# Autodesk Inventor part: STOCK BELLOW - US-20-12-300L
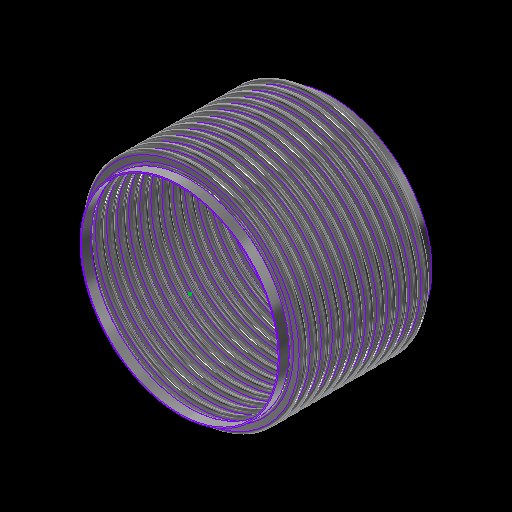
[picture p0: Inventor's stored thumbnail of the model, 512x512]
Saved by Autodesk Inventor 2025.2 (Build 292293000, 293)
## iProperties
Category: 16 GA (0.060 THICK)
RuleStatus: InUse
Created: 2024-01
Part Number: STOCK BELLOW - US-20-12-300L
Project: =STOCK BELLOWS: <Stock Number><SFILL>
Material: ASTM A240-304
Description: =STOCK BELLOWS: <Stock Number>, <SID_> I.D., <SOD_> O.D., <SPLY_> PLY, <Category>, <SNET_CONS> CONS.<PITCH_><STANGENT_> TANGENT<SFILL>
Document SubType Name: Sheet Metal
Designer: GS
Stock Number: U.S-20-12-300L
Surface Area: 31923.8 cm^2
Volume: 4820.44 cm^3
Sheet Metal Rule: Default
Appearance: STAINLESS STEEL
Mass: 38839.7 g
Density: 8.05729 g/cm^3
THK: 0.036
ID: 3.500
OD: 4.250
CONS_: 2
PITCH: 0.500
TANGENT: 0.500
BELLOWS_UPSET: 0.000
d79: 1.000
d82: 1.000
d83: 26.000
d84: 24.000
d174: 8
d214: 8
STHK_: 0.060
SID_: 20.000
SOD_: 22.500
SPITCH_: 1.125
STANGENT__: 1.000
SBELLOWS_UPSET_: 0.000
SDIFF_TAN: 1.000
d252: 2
d275: 2
d287: 0.050
d289: 0.500
d290: 0.000
SOD_NECK: 20 1/4
PLY: 1
PSET: 4.178
PBAR: 1.035
COUNTER: 1.500
NET_TUBE: 3.071
CONS: 2
S_CONS: 0
NET_CONS: 2
ID_M: 88.90 mm
OD_M: 107.95 mm
THK_M: 0.91 mm
ID_U: 3.500 in
OD_U: 4.250 in
THK_U: 0.036 in
TANGENT2: 0.500
TAN_TO_TAN: 1.000 in
d80: 2.571
d81: 10
SID: 2.375
SCONS_: 12
SPITCH: 0.250
STANGENT_: 1.000
SBELLOWS_UPSET: 0.000
SNET_CONS: 12
SS_CONS: 0
SCONS: 8
d190: 8
d191: 1
d192: 1
d193: 8
d194: 0
SIZE: 20.00
PRESSURE: 300
d230: 8
STANGENT: 4.000
SPLY_: 2
d233: 8
d234: 0
d263: 2
d265: 1
d268: 2
d269: 0
d286: 2
d288: 1
d291: 2
d292: 0
SREROLL: 0.750
BLETP: 1.000 ul
PRES_Copy: 85
MATTABLE: 20 GA (0.036 THICK)
PART_NUMBER: U.S-20-12-300L
PITCH_: =, <SPITCH_> PITCH,
CFILL: .
SFILL: .
MESH: ,
COMP: 2.27
EXT: 1.14
LAT: 0.48
ANG: 573
ASR: 7893
LSR: 29335
ANSR: 7776
PRES: 300
COMPM: 22.7
EXTM: 11.35
LATM: 4.80
ASRM: 1382.301
PRESM: 20.684
LSRM: 5137.439
ANSRM: 1361.811
TEMPMIN: 20
TEMPMAX: 800
TEMPMINM: -7
TEMPMAXM: 427
WEIGHTM: 38.840
WEIGHT: 85.627
Author: GS
Keywords: 20 GA (0.036 THICK)
Comments: =STOCK BELLOW - <STOCK NUMBER>
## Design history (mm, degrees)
sketch "Sketch2"
  geometry: L1 (0, -177.245)-(0, 562.856) reference; L2 (45.364, 0)-(44.45, 0); L3 (48.082, -2.718)-(50.343, -2.718); L4 (48.082, -3.632)-(50.343, -3.632); L5 (50.343, -9.982)-(48.082, -9.982); L6 (50.343, -9.068)-(48.082, -9.068); L7 (45.364, -12.7)-(44.45, -12.7); L8 (48.082, 0)-(48.082, -12.7); L9 (50.343, -6.35)-(53.975, -6.35); L10 (44.45, 0)-(44.45, -12.7); L11 (20.376, 102.841)-(20.376, 101.926); L12 (58.262, 457.127)-(58.262, 349.177); L13 (58.262, 444.427)-(58.262, 336.477); L14 (93.133, -58.817)-(93.133, -71.517); L15 (118.746, -66.401)-(118.746, -66.401); L16 (50.343, -9.068)-(50.343, -9.982); L17 (48.082, -9.068)-(48.082, -9.982); L18 (48.082, -9.525)-(50.343, -9.525); L19 (53.975, 0)-(53.975, -12.7); L20 (-50.343, -9.068)-(-50.343, -9.982); L21 (-50.343, -2.718)-(-48.082, -2.718); L22 (-50.343, -3.632)-(-48.082, -3.632); L23 (-48.082, -9.068)-(-50.343, -9.068); L24 (-50.343, -9.525)-(-48.082, -9.525); L25 (-48.082, -9.982)-(-50.343, -9.982); L26 (-48.082, -9.068)-(-48.082, -9.982); L27 (-44.45, 0.653)-(-44.45, -12.047); L28 (-48.082, -6.35)-(-44.45, -6.35); L29 (-50.343, 0.653)-(-50.343, -12.7); L30 (-53.061, 0)-(-53.975, 0); L31 (-53.975, 0)-(-53.975, -12.7); L32 (-53.061, -12.7)-(-53.975, -12.7); A1 r 2.718 centre (48.082, 0) between (45.364, 0) and (48.082, -2.718); A2 r 3.632 centre (48.082, 0) between (44.45, 0) and (48.082, -3.632); A3 r 3.632 centre (50.343, -6.35) between (50.343, -9.982) and (50.343, -2.718); A4 r 2.718 centre (50.343, -6.35) between (50.343, -9.068) and (50.343, -3.632); A5 r 2.718 centre (48.082, -12.7) between (48.082, -9.982) and (45.364, -12.7); A6 r 3.632 centre (48.082, -12.7) between (48.082, -9.068) and (44.45, -12.7); A7 r 3.175 centre (50.343, -6.35) between (50.343, -9.525) and (53.518, -6.35); A8 r 3.175 centre (48.082, -12.7) between (48.082, -9.525) and (44.907, -12.7); A9 r 2.718 centre (-50.343, -12.7) between (-50.343, -9.982) and (-53.061, -12.7); A10 r 2.718 centre (-48.082, -6.35) between (-48.082, -9.068) and (-48.082, -3.632); A11 r 3.175 centre (-48.082, -6.35) between (-48.082, -9.525) and (-44.907, -6.35); A12 r 3.632 centre (-48.082, -6.35) between (-48.082, -9.982) and (-48.082, -2.718); A13 r 3.175 centre (-50.343, -12.7) between (-50.343, -9.525) and (-53.518, -12.7); A14 r 3.632 centre (-50.343, -12.7) between (-50.343, -9.068) and (-53.975, -12.7); A15 r 2.718 centre (-50.343, 0) between (-53.061, 0) and (-50.343, -2.718); A16 r 3.632 centre (-50.343, 0) between (-53.975, 0) and (-50.343, -3.632); 10 further points
  constraints: 62 end point, 38 point on circle, 20 tangent, 16 centre point, 12 parallel, 9 midpoint, 7 vertical, 6 coincident, 6 concentric, 6 point on line, 4 equal radius, 4 perpendicular, 3 horizontal, 1 collinear, 1 horizontal alignment, 10 other
  dimensions: "THK" = 0.9144 distance of L11.start L11.end; "ID" = 88.9 distance of L11.end point (20.376, 13.026); "OD" = 107.95 distance of L12.start L12.end; "PITCH" = 12.7 distance of L12.start L13.start; "TANGENT" = 12.7 distance of L14.start L14.end; "BELLOWS_UPSET" = 0 distance of L15.start L15.end; "d43" = 88.9 diameter of L10 L1 (= ID); "d44" = 107.95 diameter of L9.end L1 (= OD); "d45" = 0.9144 distance between parallel lines of L5 L6 (computed from THK, PLY); "d46" = 3.6322 radius of A3 (computed from PITCH, THK, PLY); "UPSET_PITCH" = 12.7 distance of L2.end L7.end (derived); "SIDEWALL_ANGLE" = 360 deg dimension on L3 L9 (derived); "CON_GAP" = 5.4356 distance of point (48.082, -9.068) point (48.082, -3.632) (derived); "TAN1" = 4.98728 dimension on A8 (derived); "TAN2" = 4.98728 dimension on A7 (derived); "LEG1" = 2.2606 distance of L18.start L18.end (derived); "d278" = 0.9144 distance between parallel lines of L25 L23 (derived); "d279" = 3.6322 radius of A12 (derived); "d280" = 12.7 distance of L30.end L31.end (derived); "d281" = 360 deg dimension on L21 L28 (derived); "d282" = 5.4356 distance of point (-50.343, -9.068) point (-50.343, -3.632) (derived); "d283" = 4.98728 dimension on A13 (derived); "d284" = 4.98728 dimension on A11 (derived); "d285" = 2.2606 distance of L24.start L24.end (derived); "d293" = 88.9 diameter of L27 L1 (derived); "d294" = 107.95 diameter of L31 L1 (derived)
  node "Sketch Rectangular Pattern1" dims "d31" = 25.4, "ID" = 88.9
  node "Sketch Rectangular Pattern2" dims "d39" = 25.4, "PITCH" = 12.7
revolve "CONS" stored, may be unused: angle "d48" = 90 deg
node "BELLOW MIDPLANE"
pattern_linear "Rectangular Pattern2" dims "d52" = 12.7 (= UPSET_PITCH)
sketch "Sketch5"
  geometry: C1 r 45.364 at (0, 0) reference; C2 r 44.45 at (0, 0) reference
extrude "TANGENT" new body sketch "Sketch5" distance "d53" = 12.7 (= TANGENT); taper "d54" = 0 deg
revolve "SAMETAN" stored, may be unused: angle "d65" = 90 deg
revolve "DIFFTAN" stored, may be unused: angle "d70" = 90 deg
sketch "Sketch9"
  geometry: L1 (53.319, 0)-(-53.319, 0) reference; L2 (0, -17.78)-(0, 17.78) reference; L3 (38.085, 0)-(-38.085, 0); L4 (38.085, -11.906)-(38.085, 11.906); L5 (25.385, -11.906)-(25.385, 11.906); L6 (13.15, 11.906)-(13.15, -11.906); L7 (-25.385, -11.906)-(-25.385, 11.906); L8 (-38.085, -11.906)-(-38.085, 11.906); L9 (37.291, -11.906)-(37.291, 11.906); L10 (38.085, -11.906)-(37.291, -11.906); L11 (38.085, 11.906)-(37.291, 11.906); L12 (13.546, 11.906)-(12.753, 11.906); L13 (12.753, 11.906)-(12.753, -11.906); L14 (12.753, -11.906)-(13.546, -11.906); L15 (13.546, -11.906)-(13.546, 11.906); L16 (-13.546, 11.906)-(-13.546, -11.906); L17 (-13.15, 11.906)-(-13.15, -11.906); L18 (-13.546, -11.906)-(-12.753, -11.906); L19 (-12.753, -11.906)-(-12.753, 11.906); L20 (-12.753, 11.906)-(-13.546, 11.906); L21 (-38.085, -11.906)-(-37.291, -11.906); L22 (-37.291, -11.906)-(-37.291, 11.906); L23 (-37.291, 11.906)-(-38.085, 11.906); L24 (-38.085, 11.906)-(-38.085, -11.906); L25 (38.085, -0.397)-(-38.085, -0.397); L26 (-38.085, -0.397)-(-38.085, 0.397); L27 (-38.085, 0.397)-(38.085, 0.397); L28 (38.085, 0.397)-(38.085, -0.397); L29 (-38.085, 11.906)-(38.085, 11.906); L30 (38.085, 11.906)-(38.085, 12.7); L31 (38.085, 12.7)-(-38.085, 12.7); L32 (-38.085, 12.7)-(-38.085, 11.906); L33 (38.085, -11.906)-(-38.085, -11.906); L34 (-38.085, -11.906)-(-38.085, -12.7); L35 (-38.085, -12.7)-(38.085, -12.7); L36 (38.085, -12.7)-(38.085, -11.906); 30 further points
  constraints: 68 end point, 13 midpoint, 13 parallel, 8 horizontal, 7 perpendicular, 6 equal length, 3 point on line, 2 vertical, 14 other
  dimensions: "d115" = 23.8125 distance of L4.start L4.end (derived); "d116" = 12.7 distance between parallel lines of L4 L5 (derived); "d117" = 12.23516 distance between parallel lines of L5 L6 (derived); "d125" = 38.53427 distance between parallel lines of L7 L6 (derived); "d127" = 12.7 distance between parallel lines of L8 L7 (derived); "d128" = 24.93516 distance between parallel lines of L6 L4 (derived); "d130" = 76.16943 distance between parallel lines of L8 L4 (derived); "RULER_THK" = 0.79375 distance between parallel lines of L4 L9; "d135" = 0.79375 distance of L13.end L14.end (derived); "d138" = 26.29911 distance of L13.end L16.end (derived); "d143" = 0.79375 distance of L22.end L8.end (derived); "d144" = 0.79375 distance between parallel lines of L27 L25 (derived)
extrude "RULER" join sketch "Sketch9" distance "d149" = 0.79375 (derived); taper "d150" = 0 deg
extrude "BARS" join sketch "Sketch9" distance "d151" = 0.79375 (derived); taper "d152" = 0 deg
pattern_linear "Rectangular Pattern4" dims "d155" = 26.29911 (derived)
sketch "Sketch13"
  geometry: L1 (93.149, -52.467)-(93.149, -77.867); L2 (257.048, 0)-(254, 0); L3 (257.048, -28.575)-(254, -28.575); L4 (277.082, -22.955)-(262.668, -22.955); L5 (277.082, -19.907)-(262.668, -19.907); L6 (277.082, -14.287)-(285.75, -14.287); L7 (262.668, -5.62)-(277.082, -5.62); L8 (262.668, 0)-(262.668, -28.575); L9 (254, 0)-(254, -28.575); L10 (58.254, 75.069)-(58.254, -496.431); L11 (58.254, 46.494)-(58.254, -525.006); L12 (58.254, -10.656)-(58.254, -582.156); L13 (58.254, -39.231)-(58.254, -610.731); L14 (58.254, -67.806)-(58.254, -639.306); L15 (58.254, -96.381)-(58.254, -667.881); L16 (58.254, -124.956)-(58.254, -696.456); L17 (58.254, 17.919)-(58.254, -553.581); L18 (20.376, 103.45)-(20.376, 101.926); L19 (262.668, -8.668)-(277.082, -8.668); L20 (0, -856.437)-(0, 263.431) reference; L21 (-57.15, 0)-(342.9, 0) reference; A1 r 5.62 centre (262.668, 0) between (257.048, 0) and (262.668, -5.62); A2 r 5.62 centre (262.668, -28.575) between (262.668, -22.955) and (257.048, -28.575); A3 r 8.668 centre (262.668, -28.575) between (262.668, -19.907) and (254, -28.575); A4 r 5.62 centre (277.082, -14.287) between (277.082, -19.907) and (277.082, -8.668); A5 r 8.668 centre (277.082, -14.287) between (277.082, -22.955) and (277.082, -5.62); A6 r 8.668 centre (262.668, 0) between (254, 0) and (262.668, -8.668); 6 further points; 1 other entity
  constraints: 38 end point, 15 point on circle, 9 tangent, 6 centre point, 6 parallel, 5 vertical alignment, 4 point on line, 4 vertical, 3 coincident, 3 concentric, 2 collinear, 2 equal radius, 1 horizontal, 1 perpendicular, 23 other
  dimensions: "SBELLOWS_UPSET_" = 0 distance of point (118.762, -66.401) point (118.762, -66.401); "STOTAL_THK_BELLOW__" = 3.048 distance between parallel lines of L4 L5 (derived); "d224" = 8.66775 radius of A5 (derived); "d225" = 28.575 distance of L2.end L3.end (derived); "SSIDEWALL_ANGLE_" = 360 deg dimension on L7 L6 (derived); "SSCON_GAP_" = 11.2395 distance of point (262.668, -19.907) point (262.668, -8.668) (derived); "d235" = 508 diameter of L9 L20 (derived); "d236" = 571.5 diameter of L6.end L20 (derived)
  node "Sketch Rectangular Pattern4" dims "d228" = 25.4
  node "Sketch Rectangular Pattern5" dims "d229" = 25.4
revolve "SBELLOW" stored, may be unused: angle "d197" = 90 deg
pattern_linear "Rectangular Pattern5" dims "d204" = 28.575 (derived)
revolve "STANGENT" stored, may be unused: angle "d240" = 90 deg
revolve "SSAMETAN" stored, may be unused: angle "d241" = 90 deg
revolve "SDIFFTAN" stored, may be unused: angle "d246" = 90 deg
revolve "INVCON" stored, may be unused: angle "d295" = 90 deg
pattern_linear "Rectangular Pattern6" dims "d298" = 12.7 (derived)
revolve "INVTANGENT" stored, may be unused: angle "d302" = 90 deg
revolve "INVSAMETAN" stored, may be unused: angle "d307" = 90 deg
revolve "INVDIFFTAN" stored, may be unused: angle "d312" = 90 deg
sketch "ID BELLOW MOUNT CALC"
  geometry: L1 (44.45, 0)-(38.1, 0); L2 (38.1, 0)-(38.1, 12.7); L3 (38.1, 12.7)-(44.45, 12.7); L4 (44.45, 12.7)-(44.45, 0); L5 (36.513, 12.7)-(35.598, 12.7); L6 (35.598, 12.7)-(35.598, 0); L7 (35.598, 0)-(36.513, 0); L8 (36.513, 0)-(36.513, 12.7); L9 (0, -2.54)-(0, 15.24) reference; L10 (-8.89, 0)-(53.34, 0) reference; 1 further point
  constraints: 16 end point, 5 parallel, 2 collinear, 2 horizontal, 2 perpendicular
  dimensions: "d314" = 12.7 distance of L5.end L6.end (derived); "d315" = 0.9144 distance of L5.start L5.end (derived); "IG" = 1.5875 distance between parallel lines of L2 L8; "PIPE_OD" = 88.9 diameter of L4 L9; "PIPE_WALL" = 6.35 distance of L2.end L3.end; "ID_MT_BELLOW" = 71.1962 diameter of L6 L9 (derived)
revolve "CFILL" stored, may be unused: angle "d320" = 90 deg
pattern_linear "Rectangular Pattern7" dims "d323" = 12.7 (derived)
revolve "SFILL" stored, may be unused: angle "d324" = 90 deg
pattern_linear "Rectangular Pattern8" dims "d327" = 28.575 (derived)
node "STOCK BELLOW MIDPLANE"
node "BELLOW"
sketch "Sketch6"
  geometry: L1 (-12.7, 45.364)-(0, 45.364); L2 (0, 45.364)-(0, 44.45); L3 (0, 44.45)-(-12.7, 44.45); L4 (-12.7, 44.45)-(-12.7, 45.364); L5 (10.16, 0)-(-60.96, 0) reference; L6 (-38.1, -89.422)-(-38.1, 153.44) reference; 1 further point
  constraints: 8 end point, 2 parallel, 1 horizontal, 1 perpendicular
  dimensions: "d61" = 12.7 distance of L2.end L3.end (derived); "d62" = 0.9144 distance of L1.end L2.end (derived); "d63" = 88.9 diameter of L3 L5 (derived); "d64" = 25.4 distance between parallel lines of L4 L6 (derived)
sketch "Sketch12"
  geometry: 1 further point
sketch "Sketch14"
  geometry: L1 (-25.4, 257.048)-(0, 257.048); L2 (0, 257.048)-(0, 254); L3 (0, 254)-(-25.4, 254); L4 (-25.4, 254)-(-25.4, 257.048); L5 (5.08, 0)-(-30.48, 0) reference; L6 (0, -51.41)-(0, 308.458) reference; 1 further point
  constraints: 8 end point, 2 parallel, 1 collinear, 1 horizontal, 1 perpendicular
  dimensions: "d237" = 3.048 distance of L3.end L1.start (derived); "d238" = 508 diameter of L3 L5 (derived); "d239" = 25.4 distance of L1.start L1.end (derived); "SOD_NECK" = 514.096 diameter of L1 L5 (derived)
sketch "Sketch15"
  geometry: L1 (-51.41, 0)-(308.458, 0) reference; L2 (254, -342.9)-(257.048, -342.9); L3 (257.048, -342.9)-(257.048, -368.3); L4 (257.048, -368.3)-(254, -368.3); L5 (254, -368.3)-(254, -342.9); L6 (0, -444.5)-(0, 88.9) reference; 1 further point
  constraints: 8 end point, 2 parallel, 1 horizontal, 1 perpendicular
  dimensions: "d205" = 25.4 distance of L4.end L2.start (derived); "d206" = 3.048 distance of L3.end L4.end (derived); "d207" = 508 diameter of L5 L6 (derived); "d208" = 342.9 distance between parallel lines of L1 L2 (derived)
node "TANGENT_"
node "SAME_TAN"
sketch "Sketch8"
  geometry: L1 (45.364, -25.4)-(44.45, -25.4); L2 (44.45, -25.4)-(44.45, -38.1); L3 (44.45, -38.1)-(45.364, -38.1); L4 (45.364, -38.1)-(45.364, -25.4); L5 (0, -48.26)-(0, 22.86) reference; L6 (-89.422, 0)-(153.44, 0) reference; 1 further point
  constraints: 8 end point, 2 parallel, 1 horizontal, 1 perpendicular
  dimensions: "d66" = 88.9 diameter of L2 L5 (derived); "TOTAL_THK_BELLOW" = 0.9144 distance of L2.end L3.end (derived); "d68" = 25.4 distance between parallel lines of L1 L6 (derived); "d69" = 12.7 distance of L1.end L2.end (derived)
node "DIFF_TAN"
node "Sketch Rectangular Pattern3" dims "d138" = 26.29911 (derived), "d141" = 25.4
node "SBELLOW_"
node "STANGENT_"
node "SSAME_TAN"
sketch "Sketch16"
  geometry: L1 (257.048, -342.9)-(254, -342.9); L2 (254, -342.9)-(254, -368.3); L3 (254, -368.3)-(257.048, -368.3); L4 (257.048, -368.3)-(257.048, -342.9); L5 (0, -444.5)-(0, 88.9) reference; L6 (-51.41, 0)-(308.458, 0) reference; 1 further point
  constraints: 8 end point, 2 parallel, 1 horizontal, 1 perpendicular
  dimensions: "SDIFF_TAN" = 25.4 distance of L3.end L1.start; "d243" = 3.048 distance of L2.end L3.end (derived); "d244" = 342.9 distance between parallel lines of L1 L6 (derived); "d245" = 508 diameter of L2 L5 (derived)
node "SDIFF_TAN"
body "Solid15"
sketch "Sketch17"
  geometry: L1 (53.975, 12.7)-(53.061, 12.7); L2 (53.061, 12.7)-(53.061, 0); L3 (53.061, 0)-(53.975, 0); L4 (53.975, 0)-(53.975, 12.7); L5 (0, -2.54)-(0, 15.24) reference; L6 (-10.795, 0)-(64.77, 0) reference; 2 further points
  constraints: 8 end point, 2 parallel, 1 horizontal, 1 midpoint, 1 perpendicular, 1 point on line
  dimensions: "INVTANGENT" = 12.7 distance of L3.end L1.start (derived); "d300" = 0.9144 distance of L1.start L1.end (derived); "d301" = 107.95 diameter of L4 L5 (derived)
body "Solid16"
sketch "Sketch18"
  geometry: L1 (53.975, -25.4)-(53.061, -25.4); L2 (53.061, -25.4)-(53.061, -38.1); L3 (53.061, -38.1)-(53.975, -38.1); L4 (53.975, -38.1)-(53.975, -25.4); L5 (-10.795, 0)-(64.77, 0) reference; L6 (0, -48.26)-(0, 22.86) reference; 1 further point
  constraints: 8 end point, 2 parallel, 1 horizontal, 1 perpendicular
  dimensions: "d303" = 25.4 distance between parallel lines of L1 L5 (derived); "d304" = 12.7 distance of L3.end L1.start (derived); "d305" = 0.9144 distance of L2.end L3.end (derived); "d306" = 107.95 diameter of L4 L6 (derived)
body "Solid17"
sketch "Sketch19"
  geometry: L1 (53.975, -25.4)-(53.061, -25.4); L2 (53.061, -25.4)-(53.061, -38.1); L3 (53.061, -38.1)-(53.975, -38.1); L4 (53.975, -38.1)-(53.975, -25.4); L5 (0, -48.26)-(0, 22.86) reference; L6 (-10.795, 0)-(64.77, 0) reference; 1 further point
  constraints: 8 end point, 2 parallel, 1 horizontal, 1 perpendicular
  dimensions: "d308" = 12.7 distance of L1.end L2.end (derived); "d309" = 107.95 diameter of L4 L5 (derived); "d310" = 0.9144 distance of L2.end L3.end (derived); "d311" = 25.4 distance between parallel lines of L1 L6 (derived)
body "Solid18"
body "Solid19"
body "Solid20"
other parameters: "BMPL" = -171.45, "PSET" = 106.1212 (computed from OD, THK, PLY) [user parameter], "PBAR" = 26.29911 (= 0.570796 x PITCH + OD - ID) [user parameter; used in 1 equation term], "COUNTER" = 15 [user parameter], "NET_TUBE" = 77.99823 (computed from CONS_, PBAR, TANGENT) [user parameter], "S_CONS" = 0 [user parameter; used in 1 equation term], "ID_M" = 88.9 (= ID) [user parameter], "OD_M" = 107.95 (= OD) [user parameter], "THK_M" = 0.9144 (= THK) [user parameter], "ID_U" = 88.9 (= ID) [user parameter], "OD_U" = 107.95 (= OD) [user parameter], "THK_U" = 0.9144 (= THK) [user parameter], "D_UNITS" = 0 [user parameter], "TANGENT2" = 12.7 [user parameter], "TAN_TO_TAN" = 25.4 [user parameter], "OD_NECK" = 90.7288 [user parameter], "d79" = 25.4, "d80" = 65.29823 [user parameter], "d82" = 25.4, "d83" = 660.4, "d84" = 609.6, "sa_0" = 4, "FRAME_THK" = 0.79375 [user parameter], "CON_FLAT" = 12.23516 [user parameter], "SID" = 60.325 [user parameter], "SPITCH" = 6.35 [user parameter], "STANGENT_" = 25.4 [user parameter], "SBELLOWS_UPSET" = 0 [user parameter], "SS_CONS" = 0 [user parameter], "STAN_TO_TAN_" = 342.9 [user parameter], "d100" = 3.048 [user parameter], "d191" = 25.4 [user parameter], "d194" = 0 [user parameter], "STANGENT" = 101.6 [user parameter], "d234" = 0 [user parameter], "SUPSET_PITCH_" = 28.575 [user parameter], "d269" = 0 [user parameter], "d287" = 1.27, "d289" = 12.7, "d290" = 0, "d292" = 0 [user parameter], "Thickness" = 3.048 (derived), "KFactor" = 4.4, "BendRadius" = 3.048 (derived), "BendReliefWidth" = 3.048 (derived), "BendReliefDepth" = 1.524 (derived), "CornerReliefSize" = 12.192 (derived), "SeamGap" = 0.00508, "MinimumRemnant" = 6.096 (derived), "TransitionRadius" = 3.048 (derived), "JacobiRadiusSize" = 3.048 (derived), "GapSize" = 3.048 (derived), "SREROLL" = 19.05 [user parameter], "CUR_STK_PITCH" = 28.575 [user parameter], "d328" = -171.45 (derived), "ASR" = 78930 [user parameter], "LSR" = 293350 [user parameter], "ANSR" = 77760 [user parameter], "BLETP" = 1 [user parameter], "ASRM" = 13823.0109 [user parameter], "PRESM" = 206.83949 [user parameter], "LSRM" = 51374.3855 [user parameter], "ANSRM" = 13618.1088 [user parameter], "TEMPMIN" = 2664.83333 [user parameter], "TEMPMAX" = 6998.16667 [user parameter], "TEMPMINM" = 2664.83333 [user parameter], "TEMPMAXM" = 6998.16667 [user parameter], "WEIGHT" = 388.39675 [user parameter], "WEIGHTM" = 0.3884 [user parameter]
